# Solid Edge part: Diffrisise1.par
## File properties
Author: Türk
Template: Iso Part.par
Last saved by: Türk
Revision: 16
Application: Solid Edge
Accuracy: 0,990
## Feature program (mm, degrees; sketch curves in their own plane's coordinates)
pattern "PatternOccurrence_1"  XOffset = 32.7273 deg
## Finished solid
Body 1: solid body, 93 faces, 223 edges, 132 vertices.
  Faces by surface: spline 55, plane 25, cone 11, cylinder 2
  Edges by curve: curve on surface 88, line 66, circle 47, spline 22
Bounding box of the edges (mm; curved faces can reach further): 59.861 x 47.500 x 59.336, from (-29.9308, -12.5, -30) to (29.9308, 35, 29.3362).
Cylindrical faces by radius (mm): R7.5 x1, R25 x1
Conical faces (half-angle, radius in mm at the cone's reference point): 45 deg R30 x11
Planar faces by outward normal: +y 13, -y 12
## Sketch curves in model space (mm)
circle centre (0, 0, 0) radius 30
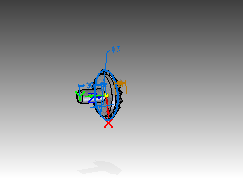
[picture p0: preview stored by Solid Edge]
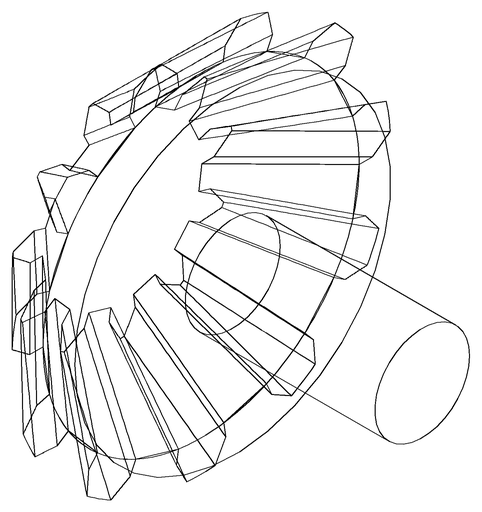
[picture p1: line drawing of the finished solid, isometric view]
